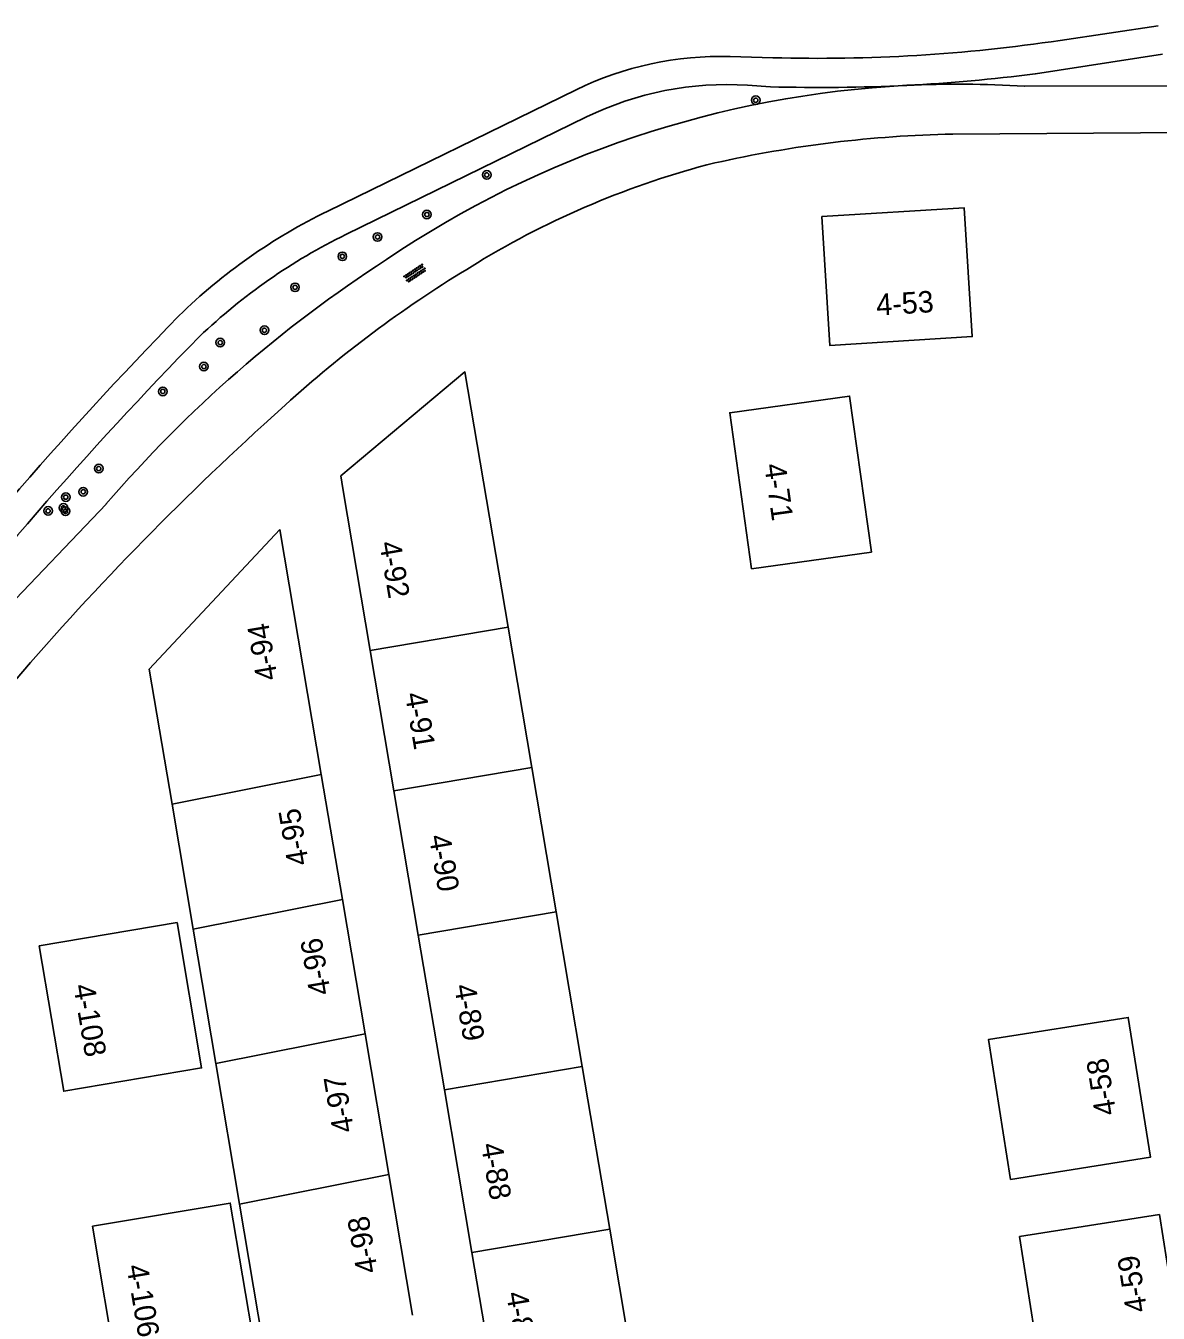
# Model space of a CAD drawing. Extents: x 134297 to 137000, y 403500 to 406000.
# Drawn here: x 136155.8 to 136261.1, y 405336.3 to 405456 of the extents above; entities that cross this region are included whole.
import ezdxf

# ---------------------------------------------------------------- set-up
doc = ezdxf.new("R2010")
doc.units = 0
for name, color, linetype in [('gg-afsc-hekwerk', 7, 'Continuous'), ('gg-knt-onverhard', 7, 'Continuous'), ('gg-knt-verharding', 7, 'Continuous'), ('gt-afsc-standplaatsafbakening', 7, 'Continuous'), ('gt-anno-standplaatsnummer', 7, 'Continuous'), ('gt-symb-boom', 7, 'Continuous'), ('gt-symb-overige verharding', 7, 'Continuous')]:
    doc.layers.add(name, color=color, linetype=linetype)

# ---------------------------------------------------------------- blocks, each defined once
blk = doc.blocks.new('gt0-BOOM')
at = {"layer": 'gt-symb-boom'}
for radius in [0.4, 0.2]:
    blk.add_circle((0, 0), radius, dxfattribs=at)
blk = doc.blocks.new('gt0-OVH')
at = {"layer": 'gt-symb-overige verharding'}
for points in [[(-0.97, 0.3), (-0.97, 0.31), (-0.96, 0.32), (-0.97, 0.33), (-0.97, 0.34), (-0.98, 0.35), (-0.99, 0.35), (-1, 0.36), (-1.01, 0.35), (-1.02, 0.35), (-1.03, 0.34), (-1.03, 0.33), (-1.04, 0.32), (-1.03, 0.31), (-1.03, 0.3), (-1.02, 0.29), (-1.01, 0.29), (-1, 0.28), (-0.99, 0.29), (-0.98, 0.29)], [(-0.87, 0.11), (-0.87, 0.12), (-0.86, 0.13), (-0.87, 0.14), (-0.87, 0.15), (-0.88, 0.16), (-0.89, 0.16), (-0.9, 0.16), (-0.91, 0.16), (-0.92, 0.16), (-0.93, 0.15), (-0.93, 0.14), (-0.94, 0.13), (-0.93, 0.12), (-0.93, 0.11), (-0.92, 0.1), (-0.91, 0.09), (-0.9, 0.09), (-0.89, 0.09), (-0.88, 0.1)], [(-0.77, 0.3), (-0.77, 0.31), (-0.76, 0.32), (-0.77, 0.33), (-0.77, 0.34), (-0.78, 0.35), (-0.79, 0.35), (-0.8, 0.36), (-0.81, 0.35), (-0.82, 0.35), (-0.83, 0.34), (-0.83, 0.33), (-0.84, 0.32), (-0.83, 0.31), (-0.83, 0.3), (-0.82, 0.29), (-0.81, 0.29), (-0.8, 0.28), (-0.79, 0.29), (-0.78, 0.29)], [(-0.67, 0.11), (-0.67, 0.12), (-0.66, 0.13), (-0.67, 0.14), (-0.67, 0.15), (-0.68, 0.16), (-0.69, 0.16), (-0.7, 0.16), (-0.71, 0.16), (-0.72, 0.16), (-0.73, 0.15), (-0.73, 0.14), (-0.74, 0.13), (-0.73, 0.12), (-0.73, 0.11), (-0.72, 0.1), (-0.71, 0.09), (-0.7, 0.09), (-0.69, 0.09), (-0.68, 0.1)], [(-0.57, 0.3), (-0.57, 0.31), (-0.56, 0.32), (-0.57, 0.33), (-0.57, 0.34), (-0.58, 0.35), (-0.59, 0.35), (-0.6, 0.36), (-0.61, 0.35), (-0.62, 0.35), (-0.63, 0.34), (-0.63, 0.33), (-0.64, 0.32), (-0.63, 0.31), (-0.63, 0.3), (-0.62, 0.29), (-0.61, 0.29), (-0.6, 0.28), (-0.59, 0.29), (-0.58, 0.29)], [(-0.47, 0.11), (-0.47, 0.12), (-0.46, 0.13), (-0.47, 0.14), (-0.47, 0.15), (-0.48, 0.16), (-0.49, 0.16), (-0.5, 0.16), (-0.51, 0.16), (-0.52, 0.16), (-0.53, 0.15), (-0.53, 0.14), (-0.54, 0.13), (-0.53, 0.12), (-0.53, 0.11), (-0.52, 0.1), (-0.51, 0.09), (-0.5, 0.09), (-0.49, 0.09), (-0.48, 0.1)], [(-0.37, 0.3), (-0.37, 0.31), (-0.36, 0.32), (-0.37, 0.33), (-0.37, 0.34), (-0.38, 0.35), (-0.39, 0.35), (-0.4, 0.36), (-0.41, 0.35), (-0.42, 0.35), (-0.43, 0.34), (-0.43, 0.33), (-0.44, 0.32), (-0.43, 0.31), (-0.43, 0.3), (-0.42, 0.29), (-0.41, 0.29), (-0.4, 0.28), (-0.39, 0.29), (-0.38, 0.29)], [(-0.27, 0.11), (-0.27, 0.12), (-0.26, 0.13), (-0.27, 0.14), (-0.27, 0.15), (-0.28, 0.16), (-0.29, 0.16), (-0.3, 0.16), (-0.31, 0.16), (-0.32, 0.16), (-0.33, 0.15), (-0.33, 0.14), (-0.34, 0.13), (-0.33, 0.12), (-0.33, 0.11), (-0.32, 0.1), (-0.31, 0.09), (-0.3, 0.09), (-0.29, 0.09), (-0.28, 0.1)], [(-0.17, 0.3), (-0.17, 0.31), (-0.16, 0.32), (-0.17, 0.33), (-0.17, 0.34), (-0.18, 0.35), (-0.19, 0.35), (-0.2, 0.36), (-0.21, 0.35), (-0.22, 0.35), (-0.23, 0.34), (-0.23, 0.33), (-0.24, 0.32), (-0.23, 0.31), (-0.23, 0.3), (-0.22, 0.29), (-0.21, 0.29), (-0.2, 0.28), (-0.19, 0.29), (-0.18, 0.29)], [(-0.07, 0.11), (-0.07, 0.12), (-0.06, 0.13), (-0.07, 0.14), (-0.07, 0.15), (-0.08, 0.16), (-0.09, 0.16), (-0.1, 0.16), (-0.11, 0.16), (-0.12, 0.16), (-0.13, 0.15), (-0.13, 0.14), (-0.14, 0.13), (-0.13, 0.12), (-0.13, 0.11), (-0.12, 0.1), (-0.11, 0.09), (-0.1, 0.09), (-0.09, 0.09), (-0.08, 0.1)], [(0.03, 0.3), (0.03, 0.31), (0.04, 0.32), (0.03, 0.33), (0.03, 0.34), (0.02, 0.35), (0.01, 0.35), (0, 0.36), (-0.01, 0.35), (-0.02, 0.35), (-0.03, 0.34), (-0.03, 0.33), (-0.04, 0.32), (-0.03, 0.31), (-0.03, 0.3), (-0.02, 0.29), (-0.01, 0.29), (0, 0.28), (0.01, 0.29), (0.02, 0.29)], [(0.13, 0.11), (0.13, 0.12), (0.14, 0.13), (0.13, 0.14), (0.13, 0.15), (0.12, 0.16), (0.11, 0.16), (0.1, 0.16), (0.09, 0.16), (0.08, 0.16), (0.07, 0.15), (0.07, 0.14), (0.06, 0.13), (0.07, 0.12), (0.07, 0.11), (0.08, 0.1), (0.09, 0.09), (0.1, 0.09), (0.11, 0.09), (0.12, 0.1)], [(0.23, 0.3), (0.23, 0.31), (0.24, 0.32), (0.23, 0.33), (0.23, 0.34), (0.22, 0.35), (0.21, 0.35), (0.2, 0.36), (0.19, 0.35), (0.18, 0.35), (0.17, 0.34), (0.17, 0.33), (0.16, 0.32), (0.17, 0.31), (0.17, 0.3), (0.18, 0.29), (0.19, 0.29), (0.2, 0.28), (0.21, 0.29), (0.22, 0.29)], [(0.33, 0.11), (0.33, 0.12), (0.34, 0.13), (0.33, 0.14), (0.33, 0.15), (0.32, 0.16), (0.31, 0.16), (0.3, 0.16), (0.29, 0.16), (0.28, 0.16), (0.27, 0.15), (0.27, 0.14), (0.26, 0.13), (0.27, 0.12), (0.27, 0.11), (0.28, 0.1), (0.29, 0.09), (0.3, 0.09), (0.31, 0.09), (0.32, 0.1)], [(0.43, 0.3), (0.43, 0.31), (0.44, 0.32), (0.43, 0.33), (0.43, 0.34), (0.42, 0.35), (0.41, 0.35), (0.4, 0.36), (0.39, 0.35), (0.38, 0.35), (0.37, 0.34), (0.37, 0.33), (0.36, 0.32), (0.37, 0.31), (0.37, 0.3), (0.38, 0.29), (0.39, 0.29), (0.4, 0.28), (0.41, 0.29), (0.42, 0.29)], [(0.53, 0.11), (0.53, 0.12), (0.54, 0.13), (0.53, 0.14), (0.53, 0.15), (0.52, 0.16), (0.51, 0.16), (0.5, 0.16), (0.49, 0.16), (0.48, 0.16), (0.47, 0.15), (0.47, 0.14), (0.46, 0.13), (0.47, 0.12), (0.47, 0.11), (0.48, 0.1), (0.49, 0.09), (0.5, 0.09), (0.51, 0.09), (0.52, 0.1)], [(0.63, 0.3), (0.63, 0.31), (0.64, 0.32), (0.63, 0.33), (0.63, 0.34), (0.62, 0.35), (0.61, 0.35), (0.6, 0.36), (0.59, 0.35), (0.58, 0.35), (0.57, 0.34), (0.57, 0.33), (0.56, 0.32), (0.57, 0.31), (0.57, 0.3), (0.58, 0.29), (0.59, 0.29), (0.6, 0.28), (0.61, 0.29), (0.62, 0.29)], [(0.73, 0.11), (0.73, 0.12), (0.74, 0.13), (0.73, 0.14), (0.73, 0.15), (0.72, 0.16), (0.71, 0.16), (0.7, 0.16), (0.69, 0.16), (0.68, 0.16), (0.67, 0.15), (0.67, 0.14), (0.66, 0.13), (0.67, 0.12), (0.67, 0.11), (0.68, 0.1), (0.69, 0.09), (0.7, 0.09), (0.71, 0.09), (0.72, 0.1)], [(0.83, 0.3), (0.83, 0.31), (0.84, 0.32), (0.83, 0.33), (0.83, 0.34), (0.82, 0.35), (0.81, 0.35), (0.8, 0.36), (0.79, 0.35), (0.78, 0.35), (0.77, 0.34), (0.77, 0.33), (0.76, 0.32), (0.77, 0.31), (0.77, 0.3), (0.78, 0.29), (0.79, 0.29), (0.8, 0.28), (0.81, 0.29), (0.82, 0.29)], [(0.93, 0.11), (0.93, 0.12), (0.94, 0.13), (0.93, 0.14), (0.93, 0.15), (0.92, 0.16), (0.91, 0.16), (0.9, 0.16), (0.89, 0.16), (0.88, 0.16), (0.87, 0.15), (0.87, 0.14), (0.86, 0.13), (0.87, 0.12), (0.87, 0.11), (0.88, 0.1), (0.89, 0.09), (0.9, 0.09), (0.91, 0.09), (0.92, 0.1)], [(1.03, 0.3), (1.03, 0.31), (1.04, 0.32), (1.03, 0.33), (1.03, 0.34), (1.02, 0.35), (1.01, 0.35), (1, 0.36), (0.99, 0.35), (0.98, 0.35), (0.97, 0.34), (0.97, 0.33), (0.96, 0.32), (0.97, 0.31), (0.97, 0.3), (0.98, 0.29), (0.99, 0.29), (1, 0.28), (1.01, 0.29), (1.02, 0.29)], [(-0.97, -0.14), (-0.97, -0.13), (-0.96, -0.12), (-0.97, -0.11), (-0.97, -0.1), (-0.98, -0.09), (-0.99, -0.09), (-1, -0.08), (-1.01, -0.09), (-1.02, -0.09), (-1.03, -0.1), (-1.03, -0.11), (-1.04, -0.12), (-1.03, -0.13), (-1.03, -0.14), (-1.02, -0.15), (-1.01, -0.15), (-1, -0.16), (-0.99, -0.15), (-0.98, -0.15)], [(-0.87, -0.33), (-0.87, -0.32), (-0.86, -0.31), (-0.87, -0.3), (-0.87, -0.29), (-0.88, -0.28), (-0.89, -0.28), (-0.9, -0.28), (-0.91, -0.28), (-0.92, -0.28), (-0.93, -0.29), (-0.93, -0.3), (-0.94, -0.31), (-0.93, -0.32), (-0.93, -0.33), (-0.92, -0.34), (-0.91, -0.35), (-0.9, -0.35), (-0.89, -0.35), (-0.88, -0.34)], [(-0.77, -0.14), (-0.77, -0.13), (-0.76, -0.12), (-0.77, -0.11), (-0.77, -0.1), (-0.78, -0.09), (-0.79, -0.09), (-0.8, -0.08), (-0.81, -0.09), (-0.82, -0.09), (-0.83, -0.1), (-0.83, -0.11), (-0.84, -0.12), (-0.83, -0.13), (-0.83, -0.14), (-0.82, -0.15), (-0.81, -0.15), (-0.8, -0.16), (-0.79, -0.15), (-0.78, -0.15)], [(-0.67, -0.33), (-0.67, -0.32), (-0.66, -0.31), (-0.67, -0.3), (-0.67, -0.29), (-0.68, -0.28), (-0.69, -0.28), (-0.7, -0.28), (-0.71, -0.28), (-0.72, -0.28), (-0.73, -0.29), (-0.73, -0.3), (-0.74, -0.31), (-0.73, -0.32), (-0.73, -0.33), (-0.72, -0.34), (-0.71, -0.35), (-0.7, -0.35), (-0.69, -0.35), (-0.68, -0.34)], [(-0.57, -0.14), (-0.57, -0.13), (-0.56, -0.12), (-0.57, -0.11), (-0.57, -0.1), (-0.58, -0.09), (-0.59, -0.09), (-0.6, -0.08), (-0.61, -0.09), (-0.62, -0.09), (-0.63, -0.1), (-0.63, -0.11), (-0.64, -0.12), (-0.63, -0.13), (-0.63, -0.14), (-0.62, -0.15), (-0.61, -0.15), (-0.6, -0.16), (-0.59, -0.15), (-0.58, -0.15)], [(-0.47, -0.33), (-0.47, -0.32), (-0.46, -0.31), (-0.47, -0.3), (-0.47, -0.29), (-0.48, -0.28), (-0.49, -0.28), (-0.5, -0.28), (-0.51, -0.28), (-0.52, -0.28), (-0.53, -0.29), (-0.53, -0.3), (-0.54, -0.31), (-0.53, -0.32), (-0.53, -0.33), (-0.52, -0.34), (-0.51, -0.35), (-0.5, -0.35), (-0.49, -0.35), (-0.48, -0.34)], [(-0.37, -0.14), (-0.37, -0.13), (-0.36, -0.12), (-0.37, -0.11), (-0.37, -0.1), (-0.38, -0.09), (-0.39, -0.09), (-0.4, -0.08), (-0.41, -0.09), (-0.42, -0.09), (-0.43, -0.1), (-0.43, -0.11), (-0.44, -0.12), (-0.43, -0.13), (-0.43, -0.14), (-0.42, -0.15), (-0.41, -0.15), (-0.4, -0.16), (-0.39, -0.15), (-0.38, -0.15)], [(-0.27, -0.33), (-0.27, -0.32), (-0.26, -0.31), (-0.27, -0.3), (-0.27, -0.29), (-0.28, -0.28), (-0.29, -0.28), (-0.3, -0.28), (-0.31, -0.28), (-0.32, -0.28), (-0.33, -0.29), (-0.33, -0.3), (-0.34, -0.31), (-0.33, -0.32), (-0.33, -0.33), (-0.32, -0.34), (-0.31, -0.35), (-0.3, -0.35), (-0.29, -0.35), (-0.28, -0.34)], [(-0.17, -0.14), (-0.17, -0.13), (-0.16, -0.12), (-0.17, -0.11), (-0.17, -0.1), (-0.18, -0.09), (-0.19, -0.09), (-0.2, -0.08), (-0.21, -0.09), (-0.22, -0.09), (-0.23, -0.1), (-0.23, -0.11), (-0.24, -0.12), (-0.23, -0.13), (-0.23, -0.14), (-0.22, -0.15), (-0.21, -0.15), (-0.2, -0.16), (-0.19, -0.15), (-0.18, -0.15)], [(-0.07, -0.33), (-0.07, -0.32), (-0.06, -0.31), (-0.07, -0.3), (-0.07, -0.29), (-0.08, -0.28), (-0.09, -0.28), (-0.1, -0.28), (-0.11, -0.28), (-0.12, -0.28), (-0.13, -0.29), (-0.13, -0.3), (-0.14, -0.31), (-0.13, -0.32), (-0.13, -0.33), (-0.12, -0.34), (-0.11, -0.35), (-0.1, -0.35), (-0.09, -0.35), (-0.08, -0.34)], [(0.03, -0.14), (0.03, -0.13), (0.04, -0.12), (0.03, -0.11), (0.03, -0.1), (0.02, -0.09), (0.01, -0.09), (0, -0.08), (-0.01, -0.09), (-0.02, -0.09), (-0.03, -0.1), (-0.03, -0.11), (-0.04, -0.12), (-0.03, -0.13), (-0.03, -0.14), (-0.02, -0.15), (-0.01, -0.15), (0, -0.16), (0.01, -0.15), (0.02, -0.15)], [(0.13, -0.33), (0.13, -0.32), (0.14, -0.31), (0.13, -0.3), (0.13, -0.29), (0.12, -0.28), (0.11, -0.28), (0.1, -0.28), (0.09, -0.28), (0.08, -0.28), (0.07, -0.29), (0.07, -0.3), (0.06, -0.31), (0.07, -0.32), (0.07, -0.33), (0.08, -0.34), (0.09, -0.35), (0.1, -0.35), (0.11, -0.35), (0.12, -0.34)], [(0.23, -0.14), (0.23, -0.13), (0.24, -0.12), (0.23, -0.11), (0.23, -0.1), (0.22, -0.09), (0.21, -0.09), (0.2, -0.08), (0.19, -0.09), (0.18, -0.09), (0.17, -0.1), (0.17, -0.11), (0.16, -0.12), (0.17, -0.13), (0.17, -0.14), (0.18, -0.15), (0.19, -0.15), (0.2, -0.16), (0.21, -0.15), (0.22, -0.15)], [(0.33, -0.33), (0.33, -0.32), (0.34, -0.31), (0.33, -0.3), (0.33, -0.29), (0.32, -0.28), (0.31, -0.28), (0.3, -0.28), (0.29, -0.28), (0.28, -0.28), (0.27, -0.29), (0.27, -0.3), (0.26, -0.31), (0.27, -0.32), (0.27, -0.33), (0.28, -0.34), (0.29, -0.35), (0.3, -0.35), (0.31, -0.35), (0.32, -0.34)], [(0.43, -0.14), (0.43, -0.13), (0.44, -0.12), (0.43, -0.11), (0.43, -0.1), (0.42, -0.09), (0.41, -0.09), (0.4, -0.08), (0.39, -0.09), (0.38, -0.09), (0.37, -0.1), (0.37, -0.11), (0.36, -0.12), (0.37, -0.13), (0.37, -0.14), (0.38, -0.15), (0.39, -0.15), (0.4, -0.16), (0.41, -0.15), (0.42, -0.15)], [(0.53, -0.33), (0.53, -0.32), (0.54, -0.31), (0.53, -0.3), (0.53, -0.29), (0.52, -0.28), (0.51, -0.28), (0.5, -0.28), (0.49, -0.28), (0.48, -0.28), (0.47, -0.29), (0.47, -0.3), (0.46, -0.31), (0.47, -0.32), (0.47, -0.33), (0.48, -0.34), (0.49, -0.35), (0.5, -0.35), (0.51, -0.35), (0.52, -0.34)], [(0.63, -0.14), (0.63, -0.13), (0.64, -0.12), (0.63, -0.11), (0.63, -0.1), (0.62, -0.09), (0.61, -0.09), (0.6, -0.08), (0.59, -0.09), (0.58, -0.09), (0.57, -0.1), (0.57, -0.11), (0.56, -0.12), (0.57, -0.13), (0.57, -0.14), (0.58, -0.15), (0.59, -0.15), (0.6, -0.16), (0.61, -0.15), (0.62, -0.15)], [(0.73, -0.33), (0.73, -0.32), (0.74, -0.31), (0.73, -0.3), (0.73, -0.29), (0.72, -0.28), (0.71, -0.28), (0.7, -0.28), (0.69, -0.28), (0.68, -0.28), (0.67, -0.29), (0.67, -0.3), (0.66, -0.31), (0.67, -0.32), (0.67, -0.33), (0.68, -0.34), (0.69, -0.35), (0.7, -0.35), (0.71, -0.35), (0.72, -0.34)], [(0.83, -0.14), (0.83, -0.13), (0.84, -0.12), (0.83, -0.11), (0.83, -0.1), (0.82, -0.09), (0.81, -0.09), (0.8, -0.08), (0.79, -0.09), (0.78, -0.09), (0.77, -0.1), (0.77, -0.11), (0.76, -0.12), (0.77, -0.13), (0.77, -0.14), (0.78, -0.15), (0.79, -0.15), (0.8, -0.16), (0.81, -0.15), (0.82, -0.15)], [(0.93, -0.33), (0.93, -0.32), (0.94, -0.31), (0.93, -0.3), (0.93, -0.29), (0.92, -0.28), (0.91, -0.28), (0.9, -0.28), (0.89, -0.28), (0.88, -0.28), (0.87, -0.29), (0.87, -0.3), (0.86, -0.31), (0.87, -0.32), (0.87, -0.33), (0.88, -0.34), (0.89, -0.35), (0.9, -0.35), (0.91, -0.35), (0.92, -0.34)], [(1.03, -0.14), (1.03, -0.13), (1.04, -0.12), (1.03, -0.11), (1.03, -0.1), (1.02, -0.09), (1.01, -0.09), (1, -0.08), (0.99, -0.09), (0.98, -0.09), (0.97, -0.1), (0.97, -0.11), (0.96, -0.12), (0.97, -0.13), (0.97, -0.14), (0.98, -0.15), (0.99, -0.15), (1, -0.16), (1.01, -0.15), (1.02, -0.15)]]:
    blk.add_lwpolyline(points, close=True, dxfattribs=at)

msp = doc.modelspace()

# ---------------------------------------------------------------- linework, layer by layer
at = {"layer": 'gg-afsc-hekwerk'}
for p, q in [((136242.02, 405445.93), (136335.28, 405446.58)), ((136196.82, 405433.35), (136197.82, 405433.96)), ((136177.95, 405418.92), (136179.94, 405420.73))]:
    msp.add_line(p, q, dxfattribs=at)
for centre, radius, start, end in [((136244.26, 405334.87), 111.08, 91.1588, 102.6768), ((136240.03, 405364.54), 81.25, 104.3544, 121.3038), ((136254.08, 405339.18), 110.21, 121.3014, 132.272), ((136357.75, 405221.11), 267.31, 132.2692, 139.8602)]:
    msp.add_arc(centre, radius, start, end, dxfattribs=at)
at = {"layer": 'gg-knt-onverhard'}
for points in [[(136379.92, 405451.37), (136352.89, 405450.53), (136248.66, 405450.37)], [(136163.29, 405411.52), (136153.6, 405401.35), (136106.47, 405341.74), (136093.27, 405323.13)]]:
    msp.add_lwpolyline(points, dxfattribs=at)
for centre, radius, start, end in [((136242.66, 405355.42), 95.17, 92.9634, 124.0648), ((136242.39, 405351.69), 98.88, 86.3611, 92.6949), ((136254.76, 405332.98), 120.56, 122.857, 139.3531)]:
    msp.add_arc(centre, radius, start, end, dxfattribs=at)
at = {"layer": 'gg-knt-verharding'}
for p, q in [((136252, 405454.64), (136261.11, 405456)), ((136249.69, 405451.53), (136261.5, 405453.35)), ((136221.32, 405453.14), (136225.28, 405453.03)), ((136183.91, 405438.77), (136206.99, 405450.04)), ((136225.06, 405450.33), (136222.92, 405450.47)), ((136207.96, 405447.52), (136185.59, 405436.59))]:
    msp.add_line(p, q, dxfattribs=at)
for centre, radius, start, end in [((136229.55, 405604.71), 151.74, 268.3847, 278.5066), ((136220.45, 405422.46), 30.69, 88.3766, 116.0268), ((136228.89, 405616.18), 165.96, 273.0545, 277.1977), ((136221, 405420.84), 29.69, 86.283, 116.0391), ((136229.67, 405616.4), 166.14, 268.4095, 272.7834), ((136207.43, 405390.61), 53.6, 116.0237, 134.1971), ((136209.31, 405388.02), 54.05, 116.0357, 133.6829), ((136445.87, 405160.3), 385.08, 135.744, 142.6886), ((136434.8, 405169.39), 368.09, 135.5613, 142.492)]:
    msp.add_arc(centre, radius, start, end, dxfattribs=at)
at = {"layer": 'gt-afsc-standplaatsafbakening'}
for p, q in [((136183.3, 405386.37), (136179.45, 405409.16)), ((136223.31, 405405.5), (136234.44, 405407.07)), ((136187.85, 405397.91), (136200.67, 405400.08)), ((136200.67, 405400.08), (136202.87, 405387.03)), ((136190.05, 405384.87), (136187.85, 405397.91)), ((136169.43, 405383.61), (136183.3, 405386.37)), ((136185.26, 405374.76), (136183.3, 405386.37)), ((136190.05, 405384.87), (136202.87, 405387.03)), ((136202.87, 405387.03), (136205.14, 405373.61)), ((136192.32, 405371.45), (136190.05, 405384.87)), ((136169.43, 405383.61), (136171.39, 405371.99)), ((136171.39, 405371.99), (136185.26, 405374.76)), ((136187.37, 405362.26), (136185.26, 405374.76)), ((136192.32, 405371.45), (136205.14, 405373.61)), ((136205.14, 405373.61), (136207.57, 405359.22)), ((136171.39, 405371.99), (136173.5, 405359.5)), ((136194.75, 405357.06), (136192.32, 405371.45)), ((136173.5, 405359.5), (136187.37, 405362.26)), ((136189.58, 405349.19), (136187.37, 405362.26)), ((136173.5, 405359.5), (136175.71, 405346.42)), ((136194.75, 405357.06), (136207.57, 405359.22)), ((136207.57, 405359.22), (136210.12, 405344.11)), ((136197.3, 405341.94), (136194.75, 405357.06)), ((136175.71, 405346.42), (136189.58, 405349.19)), ((136191.79, 405336.12), (136189.58, 405349.19)), ((136175.71, 405346.42), (136177.92, 405333.35)), ((136197.3, 405341.94), (136210.12, 405344.11)), ((136210.12, 405344.11), (136212.24, 405331.55)), ((136199.43, 405329.39), (136197.3, 405341.94))]:
    msp.add_line(p, q, dxfattribs=at)
for points in [[(136229.84, 405438.25), (136243.08, 405439.07), (136243.82, 405427.1), (136230.58, 405426.28), (136229.84, 405438.25)], [(136187.85, 405397.91), (136185.31, 405412.96), (136185.12, 405414.15), (136196.66, 405423.81), (136200.67, 405400.08)], [(136223.31, 405405.5), (136221.28, 405420.01), (136232.41, 405421.57), (136234.44, 405407.07)], [(136179.45, 405409.16), (136167.3, 405396.19), (136169.43, 405383.61)], [(136157.08, 405370.46), (136169.9, 405372.62), (136172.18, 405359.1), (136159.36, 405356.93), (136157.08, 405370.46)], [(136247.38, 405348.74), (136245.33, 405361.74), (136258.33, 405363.79), (136260.38, 405350.79), (136247.38, 405348.74)], [(136162.02, 405344.38), (136174.84, 405346.54), (136177.12, 405333.02), (136164.3, 405330.86), (136162.02, 405344.38)], [(136250.27, 405330.42), (136248.22, 405343.42), (136261.22, 405345.47), (136263.27, 405332.47), (136250.27, 405330.42)]]:
    msp.add_lwpolyline(points, dxfattribs=at)

# ---------------------------------------------------------------- block references
at = {"layer": 'gt-symb-boom'}
for p in [(136223.69, 405449.07), (136198.69, 405442.13), (136193.12, 405438.45), (136188.53, 405436.36), (136185.26, 405434.56), (136180.86, 405431.68), (136178.02, 405427.69), (136173.91, 405426.54), (136172.39, 405424.31), (136168.57, 405422), (136162.61, 405414.83), (136159.55, 405412.17), (136161.17, 405412.67), (136159.33, 405411.17), (136157.9, 405410.89), (136159.52, 405410.86)]:
    msp.add_blockref('gt0-BOOM', p, dxfattribs=at)
at = {"layer": 'gt-symb-overige verharding', "rotation": 33.62652912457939}
msp.add_blockref('gt0-OVH', (136192.02, 405432.98), dxfattribs=at)

# ---------------------------------------------------------------- texts
at = {"layer": 'gt-anno-standplaatsnummer'}
for s, rotation, p in [('4-53', 3.5451, (136234.95, 405429.05)), ('4-71', 277.9829, (136224.48, 405415.18)), ('4-92', 279.591, (136188.69, 405407.92)), ('4-94', 99.591, (136179.26, 405395.28)), ('4-91', 279.591, (136191.07, 405393.87)), ('4-95', 99.591, (136182.16, 405378.08)), ('4-90', 279.591, (136193.3, 405380.64)), ('4-96', 99.591, (136184.2, 405366.03)), ('4-108', 279.591, (136160.24, 405366.75)), ('4-89', 279.591, (136195.65, 405366.74)), ('4-58', 98.9621, (136257.22, 405354.83)), ('4-97', 99.591, (136186.36, 405353.24)), ('4-88', 279.591, (136198.14, 405351.98)), ('4-98', 99.591, (136188.57, 405340.17)), ('4-106', 279.591, (136165.18, 405340.68)), ('4-59', 98.9621, (136260.1, 405336.51)), ('4-87', 279.591, (136200.48, 405338.15))]:
    msp.add_text(s, height=2, rotation=rotation, dxfattribs=at).set_placement(p)

doc.saveas('drawing.dxf')
